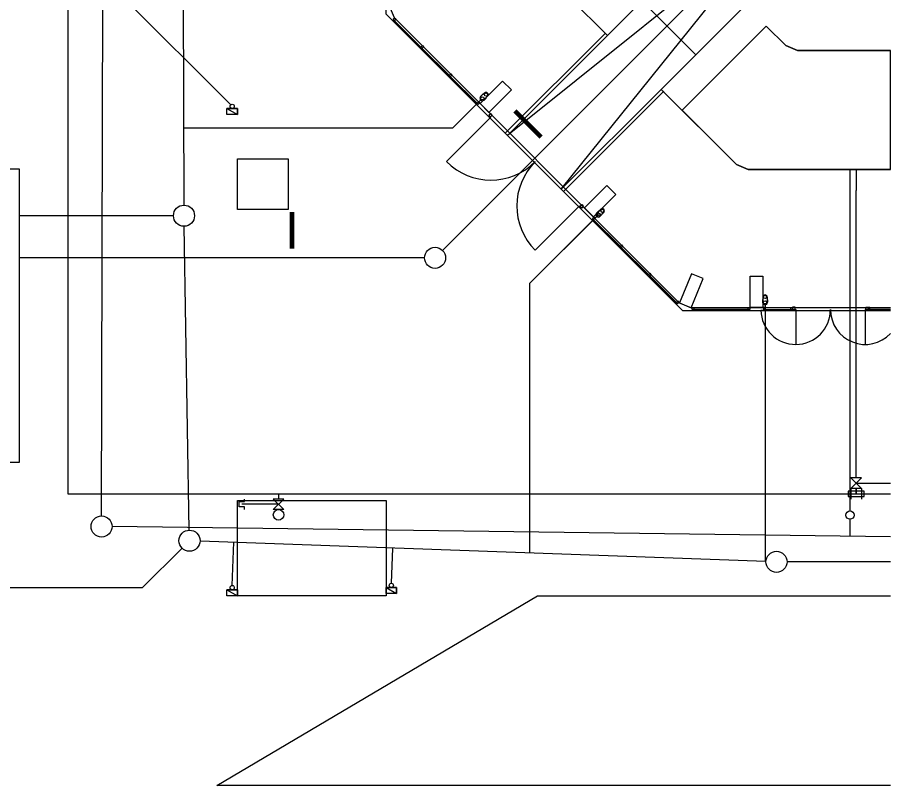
# Model space of a CAD drawing. Extents: x -264095 to -263675, y -1242370 to -1242073.
# Drawn here: x -263926.53 to -263885.11, y -1242263.98 to -1242227.54 of the extents above; entities that cross this region are included whole.
import ezdxf

# ---------------------------------------------------------------- set-up
doc = ezdxf.new("R2010")
doc.units = 0
doc.layers.add('KFA_2D_JESTVUJUCE_IS_DSP', color=7, linetype='Continuous')
doc.layers.add('KFA_2D_SITUACIA_DSP', color=7, linetype='Continuous')

msp = doc.modelspace()

# ---------------------------------------------------------------- linework, layer by layer
at = {"layer": 'KFA_2D_JESTVUJUCE_IS_DSP'}
for p, q in [((-263918.755, -1242197.225), (-263918.632, -1242236.449)), ((-263922.54, -1242251.195), (-263922.477, -1242222.753)), ((-263918.378, -1242251.867), (-263918.622, -1242237.449)), ((-263885.114, -1242252.178), (-263922.041, -1242251.701)), ((-263891.022, -1242253.354), (-263917.87, -1242252.385)), ((-263885.114, -1242253.371), (-263890.022, -1242253.372))]:
    msp.add_line(p, q, dxfattribs=at)
for centre in [(-263918.63, -1242236.949), (-263922.541, -1242251.695), (-263918.369, -1242252.367), (-263890.522, -1242253.372)]:
    msp.add_circle(centre, 0.5, dxfattribs=at)
at = {"layer": 'KFA_2D_SITUACIA_DSP'}
for p, q in [((-263924.143, -1242185.14), (-263924.143, -1242250.14)), ((-263889.023, -1242221.253), (-263906.365, -1242238.596)), ((-263916.414, -1242231.691), (-263926.24, -1242221.865)), ((-263890.391, -1242225.351), (-263894.351, -1242229.311)), ((-263908.893, -1242226.995), (-263908.663, -1242227.55)), ((-263894.351, -1242229.311), (-263896.896, -1242226.765)), ((-263908.709, -1242227.631), (-263908.638, -1242227.56)), ((-263908.68, -1242227.659), (-263908.709, -1242227.631)), ((-263908.685, -1242227.654), (-263908.703, -1242227.672)), ((-263908.703, -1242227.672), (-263907.395, -1242228.98)), ((-263907.377, -1242228.963), (-263908.685, -1242227.654)), ((-263908.652, -1242227.688), (-263908.68, -1242227.659)), ((-263908.663, -1242227.55), (-263895.135, -1242241.078)), ((-263908.581, -1242227.617), (-263908.652, -1242227.688)), ((-263908.638, -1242227.56), (-263908.581, -1242227.617)), ((-263895.005, -1242231.945), (-263891.01, -1242227.95)), ((-263891.01, -1242227.95), (-263895.005, -1242231.945)), ((-263891.01, -1242227.95), (-263890.082, -1242228.878)), ((-263890.082, -1242228.878), (-263891.01, -1242227.95)), ((-263907.395, -1242228.98), (-263907.377, -1242228.963)), ((-263907.39, -1242228.95), (-263907.319, -1242228.879)), ((-263907.361, -1242228.978), (-263907.39, -1242228.95)), ((-263907.363, -1242229.012), (-263907.345, -1242228.994)), ((-263906.055, -1242230.32), (-263907.363, -1242229.012)), ((-263907.333, -1242229.007), (-263907.361, -1242228.978)), ((-263907.345, -1242228.994), (-263906.037, -1242230.303)), ((-263907.262, -1242228.936), (-263907.333, -1242229.007)), ((-263907.319, -1242228.879), (-263907.262, -1242228.936)), ((-263890.082, -1242228.878), (-263889.528, -1242229.107)), ((-263889.528, -1242229.107), (-263890.082, -1242228.878)), ((-263889.528, -1242229.107), (-263885.114, -1242229.107)), ((-263885.114, -1242229.107), (-263889.528, -1242229.107)), ((-263885.114, -1242234.757), (-263885.114, -1242229.107)), ((-263906.037, -1242230.303), (-263906.055, -1242230.32)), ((-263906.046, -1242230.294), (-263905.975, -1242230.223)), ((-263906.017, -1242230.322), (-263906.046, -1242230.294)), ((-263906.019, -1242230.356), (-263906.001, -1242230.338)), ((-263904.711, -1242231.664), (-263906.019, -1242230.356)), ((-263905.989, -1242230.351), (-263906.017, -1242230.322)), ((-263906.001, -1242230.338), (-263904.693, -1242231.647)), ((-263905.918, -1242230.28), (-263905.989, -1242230.351)), ((-263905.975, -1242230.223), (-263905.918, -1242230.28)), ((-263903.526, -1242230.561), (-263904.586, -1242231.622)), ((-263903.101, -1242230.985), (-263903.526, -1242230.561)), ((-263904.484, -1242231.218), (-263904.563, -1242231.296)), ((-263904.465, -1242231.218), (-263904.484, -1242231.218)), ((-263904.376, -1242231.13), (-263904.465, -1242231.218)), ((-263904.162, -1242232.046), (-263903.101, -1242230.985)), ((-263904.533, -1242231.432), (-263905.894, -1242232.793)), ((-263904.726, -1242231.613), (-263904.656, -1242231.543)), ((-263904.698, -1242231.642), (-263904.726, -1242231.613)), ((-263904.693, -1242231.647), (-263904.711, -1242231.664)), ((-263904.67, -1242231.67), (-263904.698, -1242231.642)), ((-263904.599, -1242231.599), (-263904.67, -1242231.67)), ((-263904.656, -1242231.543), (-263904.599, -1242231.599)), ((-263904.586, -1242231.622), (-263904.162, -1242232.046)), ((-263904.397, -1242231.462), (-263904.319, -1242231.383)), ((-263904.319, -1242231.383), (-263904.397, -1242231.462)), ((-263904.231, -1242231.275), (-263904.319, -1242231.364)), ((-263904.319, -1242231.364), (-263904.319, -1242231.383)), ((-263916.593, -1242231.862), (-263916.093, -1242231.862)), ((-263916.593, -1242232.152), (-263916.593, -1242231.862)), ((-263916.593, -1242231.862), (-263916.093, -1242232.152)), ((-263916.593, -1242231.862), (-263916.093, -1242232.152)), ((-263916.093, -1242231.862), (-263916.593, -1242231.862)), ((-263916.093, -1242231.862), (-263916.093, -1242232.152)), ((-263916.093, -1242232.152), (-263916.093, -1242231.862)), ((-263892.422, -1242234.528), (-263895.005, -1242231.945)), ((-263895.005, -1242231.945), (-263892.422, -1242234.528)), ((-263916.093, -1242232.152), (-263916.593, -1242232.152)), ((-263904.074, -1242232.281), (-263906.177, -1242234.384)), ((-263904.091, -1242232.093), (-263904.176, -1242232.178)), ((-263904.176, -1242232.178), (-263904.091, -1242232.263)), ((-263904.006, -1242232.178), (-263904.091, -1242232.093)), ((-263904.091, -1242232.263), (-263904.006, -1242232.178)), ((-263904.091, -1242232.263), (-263904.074, -1242232.281)), ((-263905.894, -1242232.793), (-263918.643, -1242232.793)), ((-263916.093, -1242234.257), (-263913.693, -1242234.257)), ((-263916.093, -1242236.657), (-263916.093, -1242234.257)), ((-263913.693, -1242234.257), (-263913.693, -1242236.657)), ((-263891.868, -1242234.757), (-263892.422, -1242234.528)), ((-263892.422, -1242234.528), (-263891.868, -1242234.757)), ((-263926.43, -1242234.749), (-263940.33, -1242234.749)), ((-263926.43, -1242248.649), (-263926.43, -1242234.749)), ((-263885.114, -1242234.757), (-263891.868, -1242234.757)), ((-263891.868, -1242234.757), (-263885.114, -1242234.757)), ((-263887.043, -1242234.757), (-263887.043, -1242235.757)), ((-263886.743, -1242234.757), (-263886.743, -1242235.757)), ((-263899.631, -1242236.576), (-263898.571, -1242235.516)), ((-263898.571, -1242235.516), (-263898.147, -1242235.94)), ((-263887.043, -1242235.757), (-263887.043, -1242250.954)), ((-263886.743, -1242249.39), (-263886.743, -1242235.757)), ((-263898.147, -1242235.94), (-263899.207, -1242237.001)), ((-263899.866, -1242236.488), (-263901.97, -1242238.592)), ((-263899.849, -1242236.506), (-263899.764, -1242236.421)), ((-263899.764, -1242236.591), (-263899.849, -1242236.506)), ((-263899.764, -1242236.421), (-263899.679, -1242236.506)), ((-263899.679, -1242236.506), (-263899.764, -1242236.591)), ((-263899.207, -1242237.001), (-263899.631, -1242236.576)), ((-263919.13, -1242236.949), (-263926.43, -1242236.949)), ((-263913.693, -1242236.657), (-263916.093, -1242236.657)), ((-263898.965, -1242236.895), (-263902.238, -1242240.168)), ((-263899.018, -1242236.948), (-263902.238, -1242240.168)), ((-263899.185, -1242237.014), (-263899.255, -1242237.084)), ((-263899.128, -1242237.07), (-263899.185, -1242237.014)), ((-263898.969, -1242236.733), (-263899.047, -1242236.812)), ((-263898.949, -1242236.733), (-263898.969, -1242236.733)), ((-263898.861, -1242236.645), (-263898.949, -1242236.733)), ((-263898.804, -1242236.899), (-263898.882, -1242236.977)), ((-263898.882, -1242236.977), (-263898.804, -1242236.899)), ((-263898.715, -1242236.791), (-263898.804, -1242236.879)), ((-263898.804, -1242236.879), (-263898.804, -1242236.899)), ((-263899.255, -1242237.084), (-263899.227, -1242237.113)), ((-263899.232, -1242237.108), (-263899.25, -1242237.125)), ((-263899.25, -1242237.125), (-263897.942, -1242238.434)), ((-263897.924, -1242238.416), (-263899.232, -1242237.108)), ((-263899.227, -1242237.113), (-263899.199, -1242237.141)), ((-263899.199, -1242237.141), (-263899.128, -1242237.07)), ((-263897.942, -1242238.434), (-263897.924, -1242238.416)), ((-263897.865, -1242238.333), (-263897.936, -1242238.404)), ((-263897.936, -1242238.404), (-263897.908, -1242238.432)), ((-263897.908, -1242238.432), (-263897.88, -1242238.46)), ((-263897.888, -1242238.452), (-263897.906, -1242238.469)), ((-263897.906, -1242238.469), (-263896.598, -1242239.778)), ((-263896.58, -1242239.76), (-263897.888, -1242238.452)), ((-263897.88, -1242238.46), (-263897.809, -1242238.389)), ((-263897.809, -1242238.389), (-263897.865, -1242238.333)), ((-263907.219, -1242238.949), (-263926.43, -1242238.949)), ((-263896.598, -1242239.778), (-263896.58, -1242239.76)), ((-263896.522, -1242239.677), (-263896.592, -1242239.748)), ((-263896.592, -1242239.748), (-263896.564, -1242239.776)), ((-263896.566, -1242239.809), (-263896.548, -1242239.792)), ((-263895.258, -1242241.118), (-263896.566, -1242239.809)), ((-263896.564, -1242239.776), (-263896.536, -1242239.804)), ((-263896.548, -1242239.792), (-263895.24, -1242241.1)), ((-263896.536, -1242239.804), (-263896.465, -1242239.733)), ((-263896.465, -1242239.733), (-263896.522, -1242239.677)), ((-263894.551, -1242239.702), (-263895.125, -1242241.088)), ((-263894.571, -1242241.318), (-263893.997, -1242239.932)), ((-263893.997, -1242239.932), (-263894.551, -1242239.702)), ((-263891.768, -1242241.312), (-263891.768, -1242239.812)), ((-263891.768, -1242239.812), (-263891.168, -1242239.812)), ((-263891.168, -1242239.812), (-263891.168, -1242241.312)), ((-263902.238, -1242240.168), (-263902.238, -1242252.949)), ((-263895.202, -1242240.996), (-263895.273, -1242241.067)), ((-263895.273, -1242241.067), (-263895.245, -1242241.095)), ((-263895.24, -1242241.1), (-263895.258, -1242241.118)), ((-263895.245, -1242241.095), (-263895.216, -1242241.123)), ((-263895.216, -1242241.123), (-263895.146, -1242241.053)), ((-263895.146, -1242241.053), (-263895.202, -1242240.996)), ((-263895.135, -1242241.078), (-263894.581, -1242241.307)), ((-263895.125, -1242241.088), (-263894.571, -1242241.318)), ((-263891.171, -1242240.932), (-263891.185, -1242240.946)), ((-263891.185, -1242240.946), (-263891.185, -1242241.057)), ((-263891.171, -1242240.807), (-263891.171, -1242240.932)), ((-263891.068, -1242241.132), (-263891.068, -1242253.353)), ((-263890.965, -1242240.807), (-263890.965, -1242240.932)), ((-263890.965, -1242240.932), (-263890.951, -1242240.946)), ((-263890.951, -1242241.057), (-263890.951, -1242240.946)), ((-263890.951, -1242240.946), (-263890.951, -1242241.057)), ((-263894.581, -1242241.307), (-263885.114, -1242241.307)), ((-263894.531, -1242241.407), (-263894.531, -1242241.307)), ((-263894.531, -1242241.307), (-263894.451, -1242241.307)), ((-263894.491, -1242241.407), (-263894.531, -1242241.407)), ((-263894.451, -1242241.407), (-263894.491, -1242241.407)), ((-263891.828, -1242241.407), (-263894.478, -1242241.407)), ((-263894.478, -1242241.407), (-263894.478, -1242241.432)), ((-263894.478, -1242241.432), (-263891.828, -1242241.432)), ((-263894.451, -1242241.307), (-263894.451, -1242241.407)), ((-263891.868, -1242241.407), (-263891.868, -1242241.307)), ((-263891.868, -1242241.307), (-263891.788, -1242241.307)), ((-263891.828, -1242241.407), (-263891.868, -1242241.407)), ((-263891.828, -1242241.432), (-263891.828, -1242241.407)), ((-263891.788, -1242241.407), (-263891.828, -1242241.407)), ((-263891.788, -1242241.307), (-263891.788, -1242241.407)), ((-263891.168, -1242241.312), (-263891.768, -1242241.312)), ((-263891.263, -1242241.432), (-263889.613, -1242241.432)), ((-263891.058, -1242241.307), (-263891.138, -1242241.307)), ((-263891.138, -1242241.307), (-263891.138, -1242241.407)), ((-263891.138, -1242241.407), (-263891.098, -1242241.407)), ((-263891.098, -1242241.432), (-263891.098, -1242241.407)), ((-263891.098, -1242241.407), (-263889.798, -1242241.407)), ((-263891.098, -1242241.407), (-263891.058, -1242241.407)), ((-263889.798, -1242241.432), (-263891.098, -1242241.432)), ((-263891.058, -1242241.407), (-263891.058, -1242241.307)), ((-263889.838, -1242241.407), (-263889.838, -1242241.307)), ((-263889.838, -1242241.307), (-263889.758, -1242241.307)), ((-263889.798, -1242241.407), (-263889.838, -1242241.407)), ((-263889.798, -1242241.407), (-263889.798, -1242241.432)), ((-263889.758, -1242241.407), (-263889.798, -1242241.407)), ((-263889.638, -1242241.287), (-263889.758, -1242241.287)), ((-263889.758, -1242241.287), (-263889.758, -1242241.407)), ((-263889.758, -1242241.307), (-263889.758, -1242241.407)), ((-263889.758, -1242241.407), (-263889.638, -1242241.407)), ((-263889.638, -1242241.407), (-263889.638, -1242241.287)), ((-263889.638, -1242241.407), (-263889.613, -1242241.407)), ((-263889.613, -1242241.407), (-263889.613, -1242243.057)), ((-263886.288, -1242241.407), (-263886.313, -1242241.407)), ((-263886.313, -1242241.407), (-263886.313, -1242243.057)), ((-263885.114, -1242241.432), (-263886.313, -1242241.432)), ((-263886.288, -1242241.407), (-263886.288, -1242241.287)), ((-263886.288, -1242241.287), (-263886.168, -1242241.287)), ((-263886.168, -1242241.407), (-263886.288, -1242241.407)), ((-263886.168, -1242241.287), (-263886.168, -1242241.407)), ((-263886.088, -1242241.307), (-263886.168, -1242241.307)), ((-263886.168, -1242241.307), (-263886.168, -1242241.407)), ((-263886.168, -1242241.407), (-263886.128, -1242241.407)), ((-263885.114, -1242241.407), (-263886.128, -1242241.407)), ((-263886.128, -1242241.407), (-263886.128, -1242241.432)), ((-263886.128, -1242241.407), (-263886.088, -1242241.407)), ((-263886.128, -1242241.432), (-263885.114, -1242241.432)), ((-263886.088, -1242241.407), (-263886.088, -1242241.307)), ((-263940.33, -1242248.649), (-263926.43, -1242248.649)), ((-263886.493, -1242249.39), (-263886.993, -1242249.39)), ((-263886.993, -1242249.89), (-263886.493, -1242249.39)), ((-263886.993, -1242249.39), (-263886.493, -1242249.89)), ((-263886.493, -1242249.89), (-263886.993, -1242249.89)), ((-263886.993, -1242249.89), (-263886.993, -1242250.39)), ((-263886.743, -1242249.64), (-263885.114, -1242249.64)), ((-263886.743, -1242250.14), (-263886.743, -1242249.89)), ((-263886.743, -1242249.89), (-263886.743, -1242250.14)), ((-263886.493, -1242249.89), (-263886.493, -1242250.39)), ((-263924.143, -1242250.14), (-263885.114, -1242250.14)), ((-263914.143, -1242250.14), (-263914.143, -1242250.39)), ((-263914.143, -1242250.14), (-263914.143, -1242250.39)), ((-263886.368, -1242250.015), (-263887.118, -1242250.015)), ((-263887.118, -1242250.015), (-263887.118, -1242250.265)), ((-263887.118, -1242250.265), (-263886.368, -1242250.265)), ((-263886.368, -1242250.265), (-263886.368, -1242250.015)), ((-263916.093, -1242254.982), (-263916.093, -1242250.458)), ((-263916.093, -1242250.458), (-263909.043, -1242250.458)), ((-263916.018, -1242250.515), (-263915.768, -1242250.515)), ((-263916.018, -1242250.765), (-263916.018, -1242250.515)), ((-263914.143, -1242250.64), (-263915.893, -1242250.64)), ((-263915.768, -1242250.515), (-263915.768, -1242250.39)), ((-263914.393, -1242250.39), (-263913.893, -1242250.89)), ((-263913.893, -1242250.39), (-263914.393, -1242250.39)), ((-263914.393, -1242250.89), (-263913.893, -1242250.39)), ((-263909.043, -1242250.458), (-263909.043, -1242254.982)), ((-263915.768, -1242250.765), (-263916.018, -1242250.765)), ((-263915.768, -1242250.89), (-263915.768, -1242250.765)), ((-263913.893, -1242250.89), (-263914.393, -1242250.89)), ((-263887.043, -1242251.353), (-263887.043, -1242252.153)), ((-263920.595, -1242254.592), (-263918.723, -1242252.72)), ((-263916.339, -1242254.492), (-263916.265, -1242252.443)), ((-263908.789, -1242254.387), (-263908.729, -1242252.715)), ((-263929.73, -1242254.592), (-263920.595, -1242254.592)), ((-263916.593, -1242254.692), (-263916.093, -1242254.692)), ((-263916.593, -1242254.982), (-263916.593, -1242254.692)), ((-263916.593, -1242254.692), (-263916.093, -1242254.982)), ((-263916.593, -1242254.692), (-263916.093, -1242254.982)), ((-263916.093, -1242254.692), (-263916.593, -1242254.692)), ((-263916.093, -1242254.692), (-263916.093, -1242254.982)), ((-263916.093, -1242254.982), (-263916.093, -1242254.692)), ((-263909.043, -1242254.587), (-263908.543, -1242254.587)), ((-263909.043, -1242254.877), (-263909.043, -1242254.587)), ((-263909.043, -1242254.587), (-263908.543, -1242254.877)), ((-263909.043, -1242254.587), (-263908.543, -1242254.877)), ((-263908.543, -1242254.587), (-263909.043, -1242254.587)), ((-263908.543, -1242254.587), (-263908.543, -1242254.877)), ((-263908.543, -1242254.877), (-263908.543, -1242254.587)), ((-263916.093, -1242254.982), (-263916.593, -1242254.982)), ((-263909.043, -1242254.982), (-263916.093, -1242254.982)), ((-263908.543, -1242254.877), (-263909.043, -1242254.877))]:
    msp.add_line(p, q, dxfattribs=at)
for points in [[(-263885.114, -1242241.457), (-263894.968, -1242241.457), (-263909.043, -1242227.382), (-263909.043, -1242196.333), (-263914.143, -1242196.333), (-263914.143, -1242132.433), (-263909.043, -1242132.433), (-263909.043, -1242101.382), (-263894.968, -1242087.307), (-263885.114, -1242087.307)], [(-263898.543, -1242228.407), (-263902.112, -1242224.837), (-263902.343, -1242224.282), (-263902.343, -1242203.332), (-263909.043, -1242203.332)], [(-263891.673, -1242220.675), (-263894.073, -1242221.669), (-263892.937, -1242222.806), (-263898.544, -1242228.407)], [(-263895.995, -1242230.956), (-263890.391, -1242225.352), (-263889.254, -1242226.488), (-263888.26, -1242224.088), (-263891.673, -1242220.675)], [(-263903.277, -1242233.148), (-263900.731, -1242235.694), (-263890.333, -1242222.748), (-263903.277, -1242233.148)], [(-263898.65, -1242228.301), (-263903.39, -1242233.035), (-263900.629, -1242235.796), (-263895.875, -1242231.049)], [(-263898.544, -1242228.407), (-263903.281, -1242233.144), (-263900.731, -1242235.694), (-263895.982, -1242230.943)], [(-263885.114, -1242234.757), (-263891.868, -1242234.757), (-263892.424, -1242234.526), (-263895.994, -1242230.956)], [(-263885.114, -1242263.983), (-263917.08, -1242263.982), (-263901.868, -1242254.982), (-263885.114, -1242254.983)]]:
    msp.add_lwpolyline(points, dxfattribs=at)
for centre, radius in [((-263904.303, -1242231.202), 0.075), ((-263916.343, -1242231.762), 0.1), ((-263904.48, -1242231.379), 0.075), ((-263918.63, -1242236.949), 0.5), ((-263898.965, -1242236.895), 0.075), ((-263898.788, -1242236.718), 0.075), ((-263906.719, -1242238.949), 0.5), ((-263891.068, -1242240.807), 0.075), ((-263891.068, -1242241.057), 0.075), ((-263914.143, -1242251.14), 0.25), ((-263887.036, -1242251.153), 0.2), ((-263908.793, -1242254.487), 0.1), ((-263916.343, -1242254.592), 0.1)]:
    msp.add_circle(centre, radius, dxfattribs=at)
for centre, radius, start, end in [((-263904.303, -1242231.202), 0.103, 315, 135), ((-263904.48, -1242231.379), 0.117, 135, 315), ((-263904.074, -1242232.281), 2.975, 225.0001, 315.0001), ((-263899.866, -1242236.488), 2.975, 134.9999, 224.9999), ((-263898.788, -1242236.718), 0.103, 315, 135), ((-263898.965, -1242236.895), 0.117, 135, 315), ((-263891.068, -1242240.807), 0.103, 360, 180), ((-263891.068, -1242241.057), 0.117, 180, 360), ((-263889.613, -1242241.407), 1.65, 180.8682, 0), ((-263886.313, -1242241.407), 1.65, 180, 316.6103)]:
    msp.add_arc(centre, radius, start, end, dxfattribs=at)

# ---------------------------------------------------------------- texts
msp.add_text('I', height=1.75, rotation=45.0119, dxfattribs=at).set_placement((-263901.924, -1242233.448))
msp.add_text('I', height=1.75, dxfattribs=at).set_placement((-263913.835, -1242238.519))

doc.saveas('drawing.dxf')
